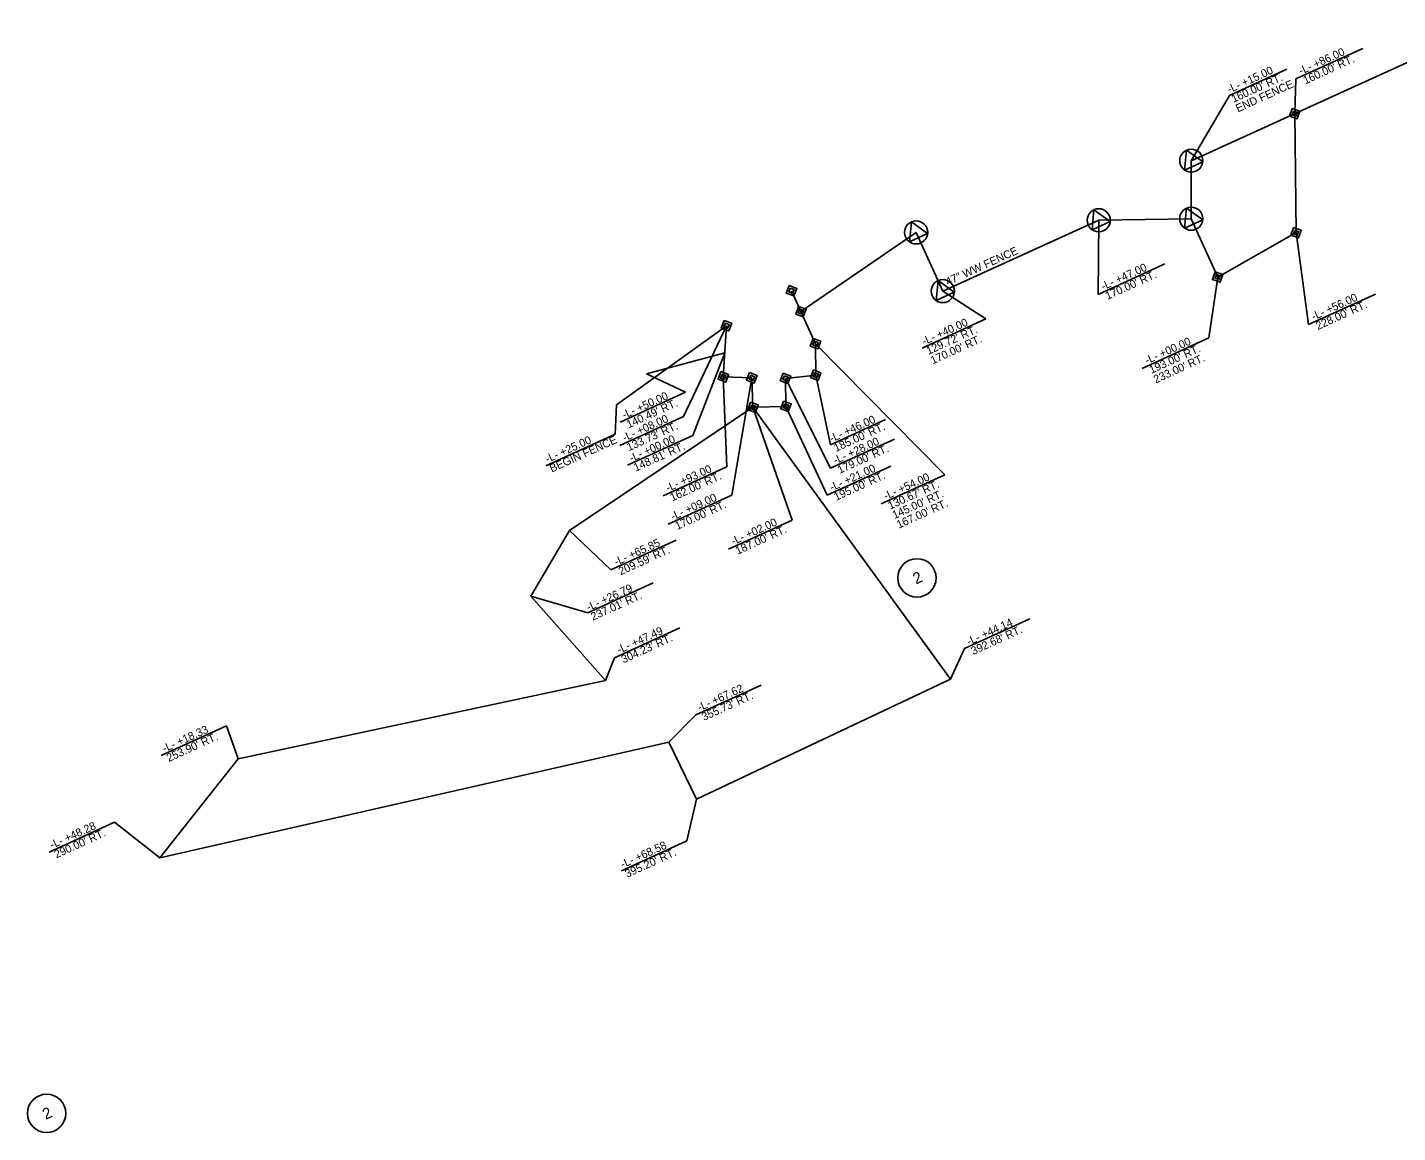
# Model space of a CAD drawing. Extents: x 2242607 to 2250377, y 661355 to 663917.
# Drawn here: x 2248219 to 2249075, y 662579 to 663269 of the extents above; entities that cross this region are included whole.
import ezdxf

# ---------------------------------------------------------------- set-up
doc = ezdxf.new("R2010")
doc.units = 0
for name, color, linetype in [('Prop Easement Construction', 7, 'Continuous'), ('Prop Easement Construction Station Offsets', 7, 'Continuous'), ('Prop Easement Permanent Drainage', 7, 'Continuous'), ('Prop Easement Permanent Drainage Station Offsets', 7, 'Continuous'), ('Prop Easement Permanent Utility', 7, 'Continuous'), ('Prop Easement Permanent Utility Station Offsets', 7, 'Continuous'), ('Prop Fence Woven Wire', 7, 'Continuous'), ('Prop Parcel Number CELL', 7, 'Continuous'), ('Prop ROW Marker CELL', 7, 'Continuous'), ('Prop ROW Permanent Easement CELL', 7, 'Continuous'), ('Prop ROW RW CA Lines', 7, 'Continuous'), ('Prop ROW Station Offsets', 7, 'Continuous')]:
    doc.layers.add(name, color=color, linetype=linetype)

msp = doc.modelspace()

# ---------------------------------------------------------------- linework, layer by layer
at = {"layer": 'Prop Easement Construction'}
for p, q in [((2248605.94, 663052.73), (2248654.9, 663065.83)), ((2248557.9, 662955.01), (2248672.52, 663031.88)), ((2248795.95, 662862.05), (2248672.52, 663031.88)), ((2248533.68, 662913.89), (2248557.9, 662955.01)), ((2248580.33, 662861.25), (2248533.68, 662913.89)), ((2248350.87, 662812.3), (2248580.33, 662861.25)), ((2248637.15, 662787.15), (2248795.95, 662862.05)), ((2248302.02, 662750.46), (2248619.95, 662822.68)), ((2248637.15, 662787.15), (2248619.95, 662822.68)), ((2248302.02, 662750.46), (2248350.87, 662812.3))]:
    msp.add_line(p, q, dxfattribs=at)
at = {"layer": 'Prop Easement Construction Station Offsets'}
for p, q in [((2248634.94, 663014.25), (2248654.9, 663065.83)), ((2248605.94, 663052.73), (2248630.46, 663041.25)), ((2248630.46, 663041.25), (2248589.63, 663022.65)), ((2248634.94, 663014.25), (2248594.12, 662995.65)), ((2248557.9, 662955.01), (2248583.72, 662930.27)), ((2248624.54, 662948.88), (2248583.72, 662930.27)), ((2248610.17, 662922.16), (2248569.34, 662903.55)), ((2248569.34, 662903.55), (2248533.68, 662913.89)), ((2248626.86, 662894.11), (2248586.04, 662875.51)), ((2248845.55, 662899.83), (2248804.73, 662881.22)), ((2248586.04, 662875.51), (2248580.33, 662861.25)), ((2248804.73, 662881.22), (2248795.95, 662862.05)), ((2248677.74, 662858.34), (2248636.91, 662839.73)), ((2248343.71, 662832.99), (2248302.88, 662814.39)), ((2248343.71, 662832.99), (2248350.87, 662812.3)), ((2248636.91, 662839.73), (2248619.95, 662822.68)), ((2248631.24, 662761.01), (2248637.15, 662787.15)), ((2248273.67, 662772.67), (2248232.85, 662754.06)), ((2248302.02, 662750.46), (2248273.67, 662772.67)), ((2248631.24, 662761.01), (2248590.41, 662742.4))]:
    msp.add_line(p, q, dxfattribs=at)
at = {"layer": 'Prop Easement Permanent Drainage'}
for p, q in [((2249011.78, 663140.96), (2249010.97, 663215.28)), ((2248946.32, 663149.67), (2248962.86, 663113.25)), ((2248702.49, 663091.63), (2248774.47, 663141.11)), ((2248962.86, 663113.25), (2249011.78, 663140.96))]:
    msp.add_line(p, q, dxfattribs=at)
at = {"layer": 'Prop Easement Permanent Drainage Station Offsets'}
for p, q in [((2249011.74, 663236.99), (2249053.52, 663256.02)), ((2249010.97, 663215.28), (2249011.74, 663236.99)), ((2249011.78, 663140.96), (2249019.66, 663083.59)), ((2248962.86, 663113.25), (2248957.34, 663075.23)), ((2249019.66, 663083.59), (2249061.43, 663102.62)), ((2248915.57, 663056.19), (2248957.34, 663075.23))]:
    msp.add_line(p, q, dxfattribs=at)
at = {"layer": 'Prop Easement Permanent Utility'}
for p, q in [((2248711.59, 663071.6), (2248696.57, 663104.68)), ((2248655.95, 663082.86), (2248653.98, 663050.92)), ((2248711.75, 663051.9), (2248711.59, 663071.6)), ((2248671.86, 663050.26), (2248653.98, 663050.92)), ((2248671.86, 663050.26), (2248672.52, 663031.88)), ((2248692.88, 663049.92), (2248711.75, 663051.9)), ((2248693.13, 663032.46), (2248692.88, 663049.92)), ((2248672.52, 663031.88), (2248693.13, 663032.46))]:
    msp.add_line(p, q, dxfattribs=at)
at = {"layer": 'Prop Easement Permanent Utility Station Offsets'}
for p, q in [((2248629.15, 663026.12), (2248655.95, 663082.86)), ((2248792.37, 662989.69), (2248711.59, 663071.6)), ((2248656.23, 662994.75), (2248653.98, 663050.92)), ((2248659.37, 662976.93), (2248671.86, 663050.26)), ((2248721.07, 662993.82), (2248692.88, 663049.92)), ((2248720.95, 663008.53), (2248711.75, 663051.9)), ((2248697.09, 662961.45), (2248672.52, 663031.88)), ((2248718.85, 662977), (2248693.13, 663032.46)), ((2248589.35, 663007.98), (2248629.15, 663026.12)), ((2248720.95, 663008.53), (2248755.34, 663024.2)), ((2248721.07, 662993.82), (2248760.86, 663011.95)), ((2248718.85, 662977), (2248758.65, 662995.14)), ((2248616.43, 662976.61), (2248656.23, 662994.75)), ((2248752.58, 662971.55), (2248792.37, 662989.69)), ((2248619.57, 662958.79), (2248659.37, 662976.93)), ((2248657.29, 662943.32), (2248697.09, 662961.45))]:
    msp.add_line(p, q, dxfattribs=at)
at = {"layer": 'Prop Fence Woven Wire'}
for p, q in [((2248946.32, 663149.67), (2248946.33, 663185.92)), ((2248888.55, 663148.69), (2248946.32, 663149.67)), ((2248702.49, 663091.63), (2248774.47, 663141.11)), ((2248774.47, 663141.11), (2248791.13, 663104.44)), ((2248791.13, 663104.44), (2248888.55, 663148.69)), ((2248711.59, 663071.6), (2248702.49, 663091.63)), ((2248655.95, 663082.86), (2248587.23, 663033.45)), ((2248655.95, 663082.86), (2248653.98, 663050.92)), ((2248711.75, 663051.9), (2248711.59, 663071.6)), ((2248653.98, 663050.92), (2248671.86, 663050.26)), ((2248671.86, 663050.26), (2248672.52, 663031.88)), ((2248692.88, 663049.92), (2248711.75, 663051.9)), ((2248693.13, 663032.46), (2248692.88, 663049.92)), ((2248672.52, 663031.88), (2248693.13, 663032.46))]:
    msp.add_line(p, q, dxfattribs=at)
at = {"layer": 'Prop Parcel Number CELL'}
for p, q in [((2248774.97, 662925.32), (2248774.97, 662925.32)), ((2248231.25, 662590.89), (2248231.25, 662590.89))]:
    msp.add_line(p, q, dxfattribs=at)
for centre in [(2248774.97, 662925.32), (2248231.25, 662590.89)]:
    msp.add_circle(centre, 12, dxfattribs=at)
at = {"layer": 'Prop ROW Marker CELL'}
for p, q in [((2249010.97, 663215.28), (2249010.97, 663215.28)), ((2248946.33, 663185.92), (2248946.33, 663185.92)), ((2248946.32, 663149.67), (2248946.32, 663149.67)), ((2248774.47, 663141.11), (2248774.47, 663141.11)), ((2248888.55, 663148.69), (2248888.55, 663148.69)), ((2249011.78, 663140.96), (2249011.78, 663140.96)), ((2248962.86, 663113.25), (2248962.86, 663113.25)), ((2248696.57, 663104.68), (2248696.57, 663104.68)), ((2248791.13, 663104.44), (2248791.13, 663104.44)), ((2248702.49, 663091.63), (2248702.49, 663091.63)), ((2248655.95, 663082.86), (2248655.95, 663082.86)), ((2248711.59, 663071.6), (2248711.59, 663071.6)), ((2248653.98, 663050.92), (2248653.98, 663050.92)), ((2248671.86, 663050.26), (2248671.86, 663050.26)), ((2248692.88, 663049.92), (2248692.88, 663049.92)), ((2248711.75, 663051.9), (2248711.75, 663051.9)), ((2248672.52, 663031.88), (2248672.52, 663031.88)), ((2248693.13, 663032.46), (2248693.13, 663032.46))]:
    msp.add_line(p, q, dxfattribs=at)
for points in [[(2248942.13, 663180.05), (2248943.34, 663192.47), (2248953.51, 663185.23)], [(2248884.36, 663142.82), (2248885.57, 663155.24), (2248895.73, 663148.01)], [(2248942.12, 663143.8), (2248943.33, 663156.22), (2248953.5, 663148.99)], [(2248770.28, 663135.24), (2248771.49, 663147.66), (2248781.65, 663140.42)], [(2248786.94, 663098.57), (2248788.15, 663110.99), (2248798.31, 663103.75)]]:
    msp.add_lwpolyline(points, close=True, dxfattribs=at)
for centre in [(2248946.33, 663185.92), (2248888.55, 663148.69), (2248946.32, 663149.67), (2248774.47, 663141.11), (2248791.13, 663104.44)]:
    msp.add_circle(centre, 7.2, dxfattribs=at)
at = {"layer": 'Prop ROW Permanent Easement CELL'}
for points in [[(2249009.48, 663218.56), (2249014.25, 663216.78), (2249012.46, 663212.01), (2249007.7, 663213.79)], [(2249010.22, 663216.92), (2249012.61, 663216.03), (2249011.72, 663213.65), (2249009.33, 663214.54)], [(2249010.29, 663144.24), (2249015.06, 663142.46), (2249013.27, 663137.69), (2249008.5, 663139.47)], [(2249011.03, 663142.6), (2249013.42, 663141.71), (2249012.53, 663139.33), (2249010.14, 663140.22)], [(2248961.37, 663116.53), (2248966.14, 663114.74), (2248964.35, 663109.98), (2248959.59, 663111.76)], [(2248962.12, 663114.89), (2248964.5, 663114), (2248963.61, 663111.61), (2248961.22, 663112.5)], [(2248695.07, 663107.95), (2248699.84, 663106.17), (2248698.06, 663101.4), (2248693.29, 663103.18)], [(2248695.82, 663106.32), (2248698.2, 663105.42), (2248697.31, 663103.04), (2248694.93, 663103.93)], [(2248701, 663094.91), (2248705.77, 663093.12), (2248703.98, 663088.36), (2248699.22, 663090.14)], [(2248701.75, 663093.27), (2248704.13, 663092.38), (2248703.24, 663089.99), (2248700.85, 663090.88)], [(2248654.46, 663086.14), (2248659.23, 663084.36), (2248657.44, 663079.59), (2248652.68, 663081.37)], [(2248655.2, 663084.5), (2248657.59, 663083.61), (2248656.7, 663081.23), (2248654.31, 663082.12)], [(2248710.1, 663074.88), (2248714.87, 663073.09), (2248713.08, 663068.33), (2248708.32, 663070.11)], [(2248710.84, 663073.24), (2248713.23, 663072.35), (2248712.34, 663069.96), (2248709.95, 663070.85)], [(2248710.26, 663055.18), (2248715.03, 663053.4), (2248713.24, 663048.63), (2248708.48, 663050.41)], [(2248652.49, 663054.2), (2248657.26, 663052.42), (2248655.48, 663047.65), (2248650.71, 663049.43)], [(2248653.24, 663052.56), (2248655.62, 663051.67), (2248654.73, 663049.29), (2248652.35, 663050.18)], [(2248670.37, 663053.53), (2248675.14, 663051.75), (2248673.35, 663046.98), (2248668.59, 663048.76)], [(2248671.11, 663051.9), (2248673.5, 663051), (2248672.61, 663048.62), (2248670.22, 663049.51)], [(2248691.39, 663053.2), (2248696.16, 663051.41), (2248694.37, 663046.65), (2248689.61, 663048.43)], [(2248692.14, 663051.56), (2248694.52, 663050.67), (2248693.63, 663048.28), (2248691.24, 663049.18)], [(2248711.01, 663053.54), (2248713.39, 663052.65), (2248712.5, 663050.27), (2248710.11, 663051.16)], [(2248671.03, 663035.16), (2248675.79, 663033.38), (2248674.01, 663028.61), (2248669.24, 663030.39)], [(2248671.77, 663033.52), (2248674.16, 663032.63), (2248673.26, 663030.25), (2248670.88, 663031.14)], [(2248691.63, 663035.73), (2248696.4, 663033.95), (2248694.62, 663029.18), (2248689.85, 663030.97)], [(2248692.38, 663034.1), (2248694.76, 663033.21), (2248693.87, 663030.82), (2248691.49, 663031.71)]]:
    msp.add_lwpolyline(points, close=True, dxfattribs=at)
at = {"layer": 'Prop ROW RW CA Lines'}
for p, q in [((2248946.33, 663185.92), (2249448.03, 663413.82)), ((2248946.32, 663149.67), (2248946.33, 663185.92)), ((2248888.55, 663148.69), (2248946.32, 663149.67)), ((2248774.47, 663141.11), (2248791.13, 663104.44)), ((2248791.13, 663104.44), (2248888.55, 663148.69))]:
    msp.add_line(p, q, dxfattribs=at)
at = {"layer": 'Prop ROW Station Offsets'}
for p, q in [((2248970.13, 663226.69), (2249006.1, 663243.08)), ((2248946.33, 663185.92), (2248970.13, 663226.69)), ((2248888.55, 663148.69), (2248888.15, 663102.39)), ((2248888.15, 663102.39), (2248929.92, 663121.42)), ((2248818.11, 663087.04), (2248791.13, 663104.44)), ((2248778.31, 663068.9), (2248818.11, 663087.04)), ((2248586.34, 663015.15), (2248587.23, 663033.45)), ((2248543.04, 662995.41), (2248586.34, 663015.15))]:
    msp.add_line(p, q, dxfattribs=at)

# ---------------------------------------------------------------- texts
at = {"layer": 'Prop Easement Construction Station Offsets'}
for s, p in [('-L- +50.00', (2248592.11, 663024.63)), ("140.49' RT.", (2248594.82, 663018.67)), ('-L- +00.00', (2248596.59, 662997.64)), ("148.81' RT.", (2248599.3, 662991.67)), ('-L- +65.85', (2248587.16, 662932.85)), ("209.59' RT.", (2248589.87, 662926.88)), ('-L- +26.79', (2248569.85, 662904.52)), ("237.01' RT.", (2248572.56, 662898.55)), ('-L- +47.49', (2248588.93, 662877.88)), ('-L- +44.14', (2248807.43, 662883.1)), ("392.68' RT.", (2248810.14, 662877.13)), ("304.23' RT.", (2248591.64, 662871.91)), ('-L- +67.62', (2248639.16, 662841.92)), ("355.73' RT.", (2248641.87, 662835.95)), ('-L- +18.33', (2248304.85, 662816.26)), ("253.90' RT.", (2248307.56, 662810.29)), ('-L- +48.28', (2248234.67, 662756.07)), ("290.00' RT.", (2248237.38, 662750.1)), ('-L- +68.58', (2248591.21, 662743.96)), ("395.20' RT.", (2248593.92, 662738))]:
    msp.add_text(s, height=5, rotation=24.43013, dxfattribs=at).set_placement(p)
at = {"layer": 'Prop Easement Permanent Drainage Station Offsets'}
for s, p in [('-L- +86.00', (2249014.87, 663239.48)), ("160.00' RT.", (2249017.59, 663233.51)), ('-L- +56.00', (2249022.79, 663086.08)), ("228.00' RT.", (2249025.5, 663080.11)), ('-L- +00.00', (2248918.7, 663058.68)), ("193.00' RT.", (2248921.41, 663052.71)), ("233.00' RT.", (2248924.12, 663046.74))]:
    msp.add_text(s, height=5, rotation=24.43013, dxfattribs=at).set_placement(p)
at = {"layer": 'Prop Easement Permanent Utility Station Offsets'}
for s, p in [('-L- +08.00', (2248592.27, 663010.36)), ("133.73' RT.", (2248594.98, 663004.39)), ('-L- +46.00', (2248721.67, 663009.91)), ("185.00' RT.", (2248724.38, 663003.94)), ('-L- +28.00', (2248723.99, 662996.2)), ("179.00' RT.", (2248726.7, 662990.23)), ('-L- +93.00', (2248619.35, 662978.99)), ('-L- +21.00', (2248721.77, 662979.38)), ("162.00' RT.", (2248622.06, 662973.03)), ("195.00' RT.", (2248724.48, 662973.41)), ('-L- +54.00', (2248755.5, 662973.93)), ('-L- +09.00', (2248622.49, 662961.17)), ("130.67' RT.", (2248758.21, 662967.96)), ("145.00' RT.", (2248760.92, 662962)), ("170.00' RT.", (2248625.2, 662955.2)), ("167.00' RT.", (2248763.63, 662956.03)), ('-L- +02.00', (2248660.21, 662945.7)), ("187.00' RT.", (2248662.92, 662939.73))]:
    msp.add_text(s, height=5, rotation=24.43013, dxfattribs=at).set_placement(p)
at = {"layer": 'Prop Fence Woven Wire'}
msp.add_text('47" WW FENCE', height=5, rotation=24.43013, dxfattribs=at).set_placement((2248794.18, 663107.74))
at = {"layer": 'Prop Parcel Number CELL'}
for p in [(2248774.35, 662921.19), (2248230.63, 662586.76)]:
    msp.add_text('2', height=7, rotation=24.49794, dxfattribs=at).set_placement(p)
at = {"layer": 'Prop ROW Station Offsets'}
for s, p in [('-L- +15.00', (2248970.09, 663227.95)), ("160.00' RT.", (2248972.8, 663221.99)), ('END FENCE', (2248975.51, 663216.02)), ('-L- +47.00', (2248891.28, 663104.87)), ("170.00' RT.", (2248893.99, 663098.91)), ('-L- +40.00', (2248779.41, 663070.57)), ("129.72' RT.", (2248782.12, 663064.6)), ("170.00' RT.", (2248784.83, 663058.63)), ('-L- +25.00', (2248544.13, 662997.08)), ('BEGIN FENCE', (2248546.84, 662991.11))]:
    msp.add_text(s, height=5, rotation=24.43013, dxfattribs=at).set_placement(p)

doc.saveas('drawing.dxf')
